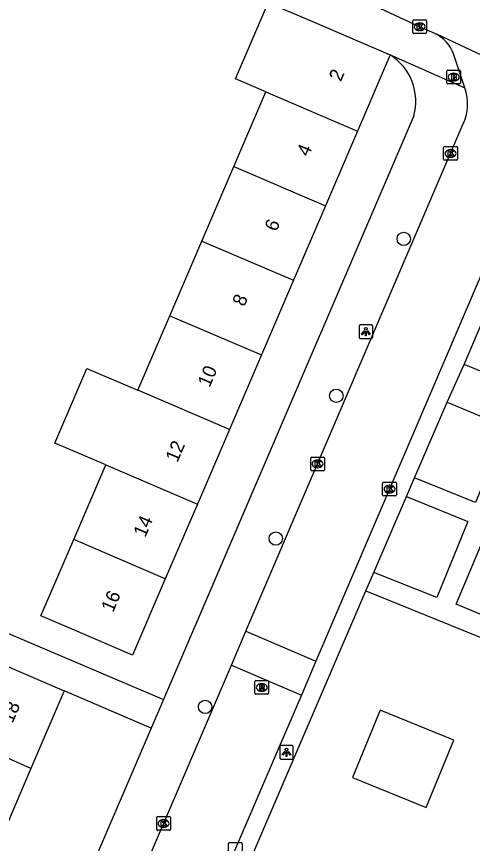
# Model space of a CAD drawing. Extents: x 159822 to 160765, y 380693 to 381634.
# Drawn here: x 160286.1 to 160319.4, y 381375.7 to 381436.2 of the extents above; entities that cross this region are included whole.
import ezdxf

# ---------------------------------------------------------------- set-up
doc = ezdxf.new("R2010")
doc.units = 0
for name, color, linetype in [('IMGEO_Boom', 7, 'Continuous'), ('IMGEO_Brandkraan', 7, 'Continuous'), ('IMGEO_Groenvoorziening', 7, 'Continuous'), ('IMGEO_Kolk', 7, 'Continuous'), ('IMGEO_Lichtpunt', 7, 'Continuous'), ('IMGEO_Pand', 7, 'Continuous'), ('IMGEO_Pand_nummerreeks', 7, 'Continuous'), ('IMGEO_Rijbaan_lokaal_open', 7, 'Continuous'), ('IMGEO_Rioolput', 7, 'Continuous'), ('IMGEO_Voetpad_halfverhard', 7, 'Continuous'), ('IMGEO_Voetpad_open', 7, 'Continuous')]:
    doc.layers.add(name, color=color, linetype=linetype)

msp = doc.modelspace()

# ---------------------------------------------------------------- linework, layer by layer
at = {"layer": 'IMGEO_Boom'}
for centre in [(160314.417, 381419.913), (160309.493, 381408.449), (160305.067, 381398.011), (160299.908, 381385.701)]:
    msp.add_circle(centre, 0.489, dxfattribs=at)
at = {"layer": 'IMGEO_Brandkraan'}
for p, q in [((160317.573, 381431.316), (160317.573, 381432.168)), ((160317.648, 381432.242), (160318.5, 381432.242)), ((160318.061, 381432.022), (160318.086, 381432.022)), ((160318.574, 381432.168), (160318.574, 381431.316)), ((160318.084, 381431.462), (160318.059, 381431.462)), ((160318.5, 381431.242), (160317.648, 381431.242))]:
    msp.add_line(p, q, dxfattribs=at)
for points in [[(160317.573, 381431.316), (160317.573, 381432.168)], [(160317.648, 381432.242), (160318.5, 381432.242)], [(160318.574, 381432.168), (160318.574, 381431.316)], [(160317.921, 381431.942), (160317.921, 381431.542), (160318.134, 381431.542)], [(160318.152, 381431.942), (160317.921, 381431.942)], [(160318.1, 381431.861), (160318.046, 381431.861), (160318.046, 381431.785)], [(160318.046, 381431.785), (160318.099, 381431.785)], [(160318.108, 381431.709), (160318.046, 381431.709), (160318.046, 381431.628)], [(160318.046, 381431.628), (160318.108, 381431.628)], [(160318.5, 381431.242), (160317.648, 381431.242)]]:
    msp.add_lwpolyline(points, dxfattribs=at)
for centre, radius, start, end in [((160317.65, 381432.166), 0.0765, 91.55205, 178.44795), ((160317.65, 381432.166), 0.0765, 91.55205, 178.44795), ((160318.498, 381432.166), 0.0765, 1.55205, 88.44795), ((160318.498, 381432.166), 0.0765, 1.55205, 88.44795), ((160318.101, 381431.823), 0.0379, 267.82845, 90.93552), ((160318.109, 381431.668), 0.0404, 269.87594, 90.50774), ((160318.14, 381431.793), 0.251, 268.66757, 293.53466), ((160318.156, 381431.797), 0.145, 59.4692, 91.53667), ((160318.181, 381431.844), 0.0922, 285.51372, 58.15012), ((160318.186, 381431.652), 0.105, 301.31148, 78.98903), ((160317.65, 381431.318), 0.0765, 181.55205, 268.44795), ((160317.65, 381431.318), 0.0765, 181.55205, 268.44795), ((160318.498, 381431.318), 0.0765, 271.55205, 358.44795), ((160318.498, 381431.318), 0.0765, 271.55205, 358.44795)]:
    msp.add_arc(centre, radius, start, end, dxfattribs=at)
for centre, major_axis, ratio, start_param, end_param in [((160318.06, 381431.742), (-0.387, 0.002), 0.722429, 4.712389, 7.853982), ((160318.085, 381431.742), (-0.39, 0.002), 0.717154, 1.570796, 4.712389)]:
    msp.add_ellipse(centre, major_axis=major_axis, ratio=ratio, start_param=start_param, end_param=end_param, dxfattribs=at)
at = {"layer": 'IMGEO_Groenvoorziening'}
msp.add_lwpolyline([(160318.08, 381383.265), (160312.7, 381385.47), (160310.683, 381380.55), (160316.062, 381378.345), (160318.08, 381383.265)], dxfattribs=at)
at = {"layer": 'IMGEO_Kolk'}
for p, q in [((160315.082, 381435), (160315.082, 381435.852)), ((160315.157, 381435.926), (160316.009, 381435.926)), ((160315.57, 381435.706), (160315.595, 381435.706)), ((160316.083, 381435.852), (160316.083, 381435)), ((160315.593, 381435.146), (160315.568, 381435.146)), ((160316.009, 381434.926), (160315.157, 381434.926)), ((160317.336, 381425.736), (160317.336, 381426.588)), ((160317.411, 381426.662), (160318.263, 381426.662)), ((160318.337, 381426.588), (160318.337, 381425.736)), ((160317.824, 381426.442), (160317.849, 381426.442)), ((160318.263, 381425.662), (160317.411, 381425.662)), ((160317.847, 381425.882), (160317.822, 381425.882)), ((160307.621, 381403.041), (160307.621, 381403.893)), ((160307.696, 381403.967), (160308.548, 381403.967)), ((160308.109, 381403.747), (160308.134, 381403.747)), ((160308.622, 381403.893), (160308.622, 381403.041)), ((160308.548, 381402.967), (160307.696, 381402.967)), ((160308.132, 381403.187), (160308.107, 381403.187)), ((160312.879, 381401.199), (160312.879, 381402.051)), ((160312.954, 381402.125), (160313.806, 381402.125)), ((160313.367, 381401.905), (160313.392, 381401.905)), ((160313.88, 381402.051), (160313.88, 381401.199)), ((160313.39, 381401.345), (160313.365, 381401.345)), ((160313.806, 381401.125), (160312.954, 381401.125)), ((160296.368, 381376.754), (160296.368, 381377.606)), ((160296.443, 381377.68), (160297.295, 381377.68)), ((160297.369, 381377.606), (160297.369, 381376.754)), ((160296.856, 381377.46), (160296.881, 381377.46)), ((160297.295, 381376.68), (160296.443, 381376.68)), ((160296.879, 381376.9), (160296.854, 381376.9)), ((160301.681, 381375.794), (160302.533, 381375.794)), ((160301.606, 381374.868), (160301.606, 381375.72)), ((160302.607, 381375.72), (160302.607, 381374.868))]:
    msp.add_line(p, q, dxfattribs=at)
for points in [[(160315.082, 381435), (160315.082, 381435.852)], [(160315.157, 381435.926), (160316.009, 381435.926)], [(160315.403, 381435.626), (160315.526, 381435.626), (160315.526, 381435.475), (160315.656, 381435.626), (160315.82, 381435.626), (160315.674, 381435.475), (160315.827, 381435.226), (160315.675, 381435.226), (160315.59, 381435.39), (160315.526, 381435.323), (160315.526, 381435.226), (160315.403, 381435.226), (160315.403, 381435.626)], [(160316.083, 381435.852), (160316.083, 381435)], [(160316.009, 381434.926), (160315.157, 381434.926)], [(160317.336, 381425.736), (160317.336, 381426.588)], [(160317.411, 381426.662), (160318.263, 381426.662)], [(160318.337, 381426.588), (160318.337, 381425.736)], [(160317.657, 381426.362), (160317.78, 381426.362), (160317.78, 381426.211), (160317.91, 381426.362), (160318.074, 381426.362), (160317.928, 381426.211), (160318.081, 381425.962), (160317.929, 381425.962), (160317.844, 381426.126), (160317.78, 381426.059), (160317.78, 381425.962), (160317.657, 381425.962), (160317.657, 381426.362)], [(160318.263, 381425.662), (160317.411, 381425.662)], [(160307.621, 381403.041), (160307.621, 381403.893)], [(160307.696, 381403.967), (160308.548, 381403.967)], [(160307.942, 381403.667), (160308.065, 381403.667), (160308.065, 381403.516), (160308.195, 381403.667), (160308.359, 381403.667), (160308.213, 381403.516), (160308.366, 381403.267), (160308.214, 381403.267), (160308.129, 381403.431), (160308.065, 381403.364), (160308.065, 381403.267), (160307.942, 381403.267), (160307.942, 381403.667)], [(160308.622, 381403.893), (160308.622, 381403.041)], [(160308.548, 381402.967), (160307.696, 381402.967)], [(160312.879, 381401.199), (160312.879, 381402.051)], [(160312.954, 381402.125), (160313.806, 381402.125)], [(160313.2, 381401.825), (160313.323, 381401.825), (160313.323, 381401.674), (160313.453, 381401.825), (160313.617, 381401.825), (160313.471, 381401.674), (160313.624, 381401.425), (160313.472, 381401.425), (160313.387, 381401.589), (160313.323, 381401.522), (160313.323, 381401.425), (160313.2, 381401.425), (160313.2, 381401.825)], [(160313.88, 381402.051), (160313.88, 381401.199)], [(160313.806, 381401.125), (160312.954, 381401.125)], [(160296.368, 381376.754), (160296.368, 381377.606)], [(160296.443, 381377.68), (160297.295, 381377.68)], [(160297.369, 381377.606), (160297.369, 381376.754)], [(160296.689, 381377.38), (160296.812, 381377.38), (160296.812, 381377.229), (160296.942, 381377.38), (160297.106, 381377.38), (160296.96, 381377.229), (160297.113, 381376.98), (160296.961, 381376.98), (160296.876, 381377.144), (160296.812, 381377.077), (160296.812, 381376.98), (160296.689, 381376.98), (160296.689, 381377.38)], [(160297.295, 381376.68), (160296.443, 381376.68)], [(160301.681, 381375.794), (160302.533, 381375.794)], [(160301.606, 381374.868), (160301.606, 381375.72)], [(160302.607, 381375.72), (160302.607, 381374.868)]]:
    msp.add_lwpolyline(points, dxfattribs=at)
for centre, start, end in [((160315.159, 381435.85), 91.55205, 178.44795), ((160315.159, 381435.85), 91.55205, 178.44795), ((160316.007, 381435.85), 1.55205, 88.44795), ((160316.007, 381435.85), 1.55205, 88.44795), ((160315.159, 381435.002), 181.55205, 268.44795), ((160315.159, 381435.002), 181.55205, 268.44795), ((160316.007, 381435.002), 271.55205, 358.44795), ((160316.007, 381435.002), 271.55205, 358.44795), ((160317.413, 381426.586), 91.55205, 178.44795), ((160317.413, 381426.586), 91.55205, 178.44795), ((160318.261, 381426.586), 1.55205, 88.44795), ((160318.261, 381426.586), 1.55205, 88.44795), ((160317.413, 381425.738), 181.55205, 268.44795), ((160317.413, 381425.738), 181.55205, 268.44795), ((160318.261, 381425.738), 271.55205, 358.44795), ((160318.261, 381425.738), 271.55205, 358.44795), ((160307.698, 381403.891), 91.55205, 178.44795), ((160307.698, 381403.891), 91.55205, 178.44795), ((160308.546, 381403.891), 1.55205, 88.44795), ((160308.546, 381403.891), 1.55205, 88.44795), ((160307.698, 381403.043), 181.55205, 268.44795), ((160307.698, 381403.043), 181.55205, 268.44795), ((160308.546, 381403.043), 271.55205, 358.44795), ((160308.546, 381403.043), 271.55205, 358.44795), ((160312.956, 381402.049), 91.55205, 178.44795), ((160312.956, 381402.049), 91.55205, 178.44795), ((160313.804, 381402.049), 1.55205, 88.44795), ((160313.804, 381402.049), 1.55205, 88.44795), ((160312.956, 381401.201), 181.55205, 268.44795), ((160312.956, 381401.201), 181.55205, 268.44795), ((160313.804, 381401.201), 271.55205, 358.44795), ((160313.804, 381401.201), 271.55205, 358.44795), ((160296.445, 381377.604), 91.55205, 178.44795), ((160296.445, 381377.604), 91.55205, 178.44795), ((160297.293, 381377.604), 1.55205, 88.44795), ((160297.293, 381377.604), 1.55205, 88.44795), ((160296.445, 381376.756), 181.55205, 268.44795), ((160296.445, 381376.756), 181.55205, 268.44795), ((160297.293, 381376.756), 271.55205, 358.44795), ((160297.293, 381376.756), 271.55205, 358.44795), ((160301.683, 381375.718), 91.55205, 178.44795), ((160301.683, 381375.718), 91.55205, 178.44795), ((160302.531, 381375.718), 1.55205, 88.44795), ((160302.531, 381375.718), 1.55205, 88.44795)]:
    msp.add_arc(centre, 0.0765, start, end, dxfattribs=at)
for centre, major_axis, ratio, start_param, end_param in [((160315.569, 381435.426), (-0.387, 0.002), 0.722429, 4.712389, 7.853982), ((160315.594, 381435.426), (-0.39, 0.002), 0.717154, 1.570796, 4.712389), ((160317.823, 381426.162), (-0.387, 0.002), 0.722429, 4.712389, 7.853982), ((160317.848, 381426.162), (-0.39, 0.002), 0.717154, 1.570796, 4.712389), ((160308.108, 381403.467), (-0.387, 0.002), 0.722429, 4.712389, 7.853982), ((160308.133, 381403.467), (-0.39, 0.002), 0.717154, 1.570796, 4.712389), ((160313.366, 381401.625), (-0.387, 0.002), 0.722429, 4.712389, 7.853982), ((160313.391, 381401.625), (-0.39, 0.002), 0.717154, 1.570796, 4.712389), ((160296.855, 381377.18), (-0.387, 0.002), 0.722429, 4.712389, 7.853982), ((160296.88, 381377.18), (-0.39, 0.002), 0.717154, 1.570796, 4.712389)]:
    msp.add_ellipse(centre, major_axis=major_axis, ratio=ratio, start_param=start_param, end_param=end_param, dxfattribs=at)
at = {"layer": 'IMGEO_Lichtpunt'}
for p, q in [((160311.155, 381413.539), (160311.155, 381412.732)), ((160311.155, 381413.539), (160311.155, 381412.732)), ((160312.057, 381413.634), (160311.249, 381413.634)), ((160312.057, 381413.634), (160311.249, 381413.634)), ((160312.151, 381412.732), (160312.151, 381413.539)), ((160312.151, 381412.732), (160312.151, 381413.539)), ((160311.249, 381412.638), (160312.057, 381412.638)), ((160311.249, 381412.638), (160312.057, 381412.638)), ((160305.355, 381382.791), (160305.355, 381381.984)), ((160305.355, 381382.791), (160305.355, 381381.984)), ((160306.257, 381382.886), (160305.449, 381382.886)), ((160306.257, 381382.886), (160305.449, 381382.886)), ((160306.351, 381381.984), (160306.351, 381382.791)), ((160306.351, 381381.984), (160306.351, 381382.791)), ((160305.449, 381381.89), (160306.257, 381381.89)), ((160305.449, 381381.89), (160306.257, 381381.89))]:
    msp.add_line(p, q, dxfattribs=at)
for points in [[(160311.529, 381413.203), (160311.568, 381413.175), (160311.38, 381412.913), (160311.342, 381412.94), (160311.529, 381413.203)], [(160311.631, 381413.155), (160311.678, 381413.155), (160311.678, 381412.833), (160311.631, 381412.833), (160311.631, 381413.155)], [(160311.741, 381413.175), (160311.779, 381413.202), (160311.966, 381412.94), (160311.927, 381412.912), (160311.741, 381413.175)], [(160305.729, 381382.455), (160305.768, 381382.427), (160305.58, 381382.165), (160305.542, 381382.192), (160305.729, 381382.455)], [(160305.831, 381382.407), (160305.878, 381382.407), (160305.878, 381382.085), (160305.831, 381382.085), (160305.831, 381382.407)], [(160305.941, 381382.427), (160305.979, 381382.454), (160306.166, 381382.192), (160306.127, 381382.164), (160305.941, 381382.427)]]:
    msp.add_lwpolyline(points, dxfattribs=at)
for centre in [(160311.654, 381413.337), (160305.854, 381382.589)]:
    msp.add_circle(centre, 0.0994, dxfattribs=at)
for centre, start, end in [((160311.249, 381413.539), 90, 180), ((160311.249, 381413.539), 90, 180), ((160312.057, 381413.539), 0, 90), ((160312.057, 381413.539), 0, 90), ((160311.249, 381412.732), 180, 270), ((160311.249, 381412.732), 180, 270), ((160312.057, 381412.732), 270, 0), ((160312.057, 381412.732), 270, 360), ((160305.449, 381382.791), 90, 180), ((160305.449, 381382.791), 90, 180), ((160306.257, 381382.791), 0, 90), ((160306.257, 381382.791), 0, 90), ((160305.449, 381381.984), 180, 270), ((160305.449, 381381.984), 180, 270), ((160306.257, 381381.984), 270, 0), ((160306.257, 381381.984), 270, 360)]:
    msp.add_arc(centre, 0.0946, start, end, dxfattribs=at)
at = {"layer": 'IMGEO_Pand'}
for points in [[(160304.341, 381430.67), (160302.13, 381431.618), (160304.52, 381437.183), (160306.728, 381436.236)], [(160306.728, 381436.236), (160313.423, 381433.365)], [(160313.423, 381433.365), (160311.036, 381427.8)], [(160302.002, 381425.214), (160304.341, 381430.67)], [(160304.341, 381430.67), (160311.036, 381427.8)], [(160311.036, 381427.8), (160308.697, 381422.344)], [(160299.662, 381419.759), (160302.002, 381425.214)], [(160302.002, 381425.214), (160308.697, 381422.344)], [(160308.697, 381422.344), (160306.357, 381416.888)], [(160297.323, 381414.303), (160299.662, 381419.759)], [(160299.662, 381419.759), (160306.357, 381416.888)], [(160306.357, 381416.888), (160304.018, 381411.433)], [(160294.983, 381408.847), (160297.323, 381414.303)], [(160297.323, 381414.303), (160304.018, 381411.433)], [(160304.018, 381411.433), (160301.678, 381405.977)], [(160292.644, 381403.393), (160288.918, 381404.991), (160291.257, 381410.444), (160294.983, 381408.847)], [(160301.678, 381405.977), (160294.983, 381408.847)], [(160301.678, 381405.977), (160299.339, 381400.522)], [(160290.304, 381397.937), (160292.644, 381403.393)], [(160292.644, 381403.393), (160299.339, 381400.522)], [(160299.339, 381400.522), (160297, 381395.067)], [(160297, 381395.067), (160294.611, 381389.497), (160290.016, 381391.468), (160287.916, 381392.368), (160290.304, 381397.937)], [(160297, 381395.067), (160290.304, 381397.937)], [(160282.945, 381389.736), (160285.019, 381388.847), (160289.614, 381386.877)], [(160289.614, 381386.877), (160287.184, 381381.211)], [(160287.184, 381381.211), (160280.556, 381384.165)], [(160287.184, 381381.211), (160284.845, 381375.755)]]:
    msp.add_lwpolyline(points, dxfattribs=at)
at = {"layer": 'IMGEO_Rijbaan_lokaal_open'}
for points in [[(160316.693, 381434.93), (160315.583, 381435.427), (160298.734, 381443.299), (160298.42, 381443.452)], [(160316.693, 381434.93), (160316.801, 381434.899), (160331.345, 381428.063)], [(160318.874, 381430.953), (160318.052, 381433.435)], [(160302.891, 381391.245), (160318.741, 381428.27)], [(160323.46, 381425.204), (160308.006, 381389.055)], [(160301.828, 381388.763), (160302.891, 381391.245)], [(160302.891, 381391.245), (160308.006, 381389.055)], [(160308.006, 381389.055), (160306.945, 381386.573)], [(160277.958, 381333.106), (160288.047, 381356.571), (160301.828, 381388.763)], [(160301.828, 381388.763), (160306.945, 381386.573)], [(160306.945, 381386.573), (160305.25, 381382.609), (160283.033, 381330.923)]]:
    msp.add_lwpolyline(points, dxfattribs=at)
for centre, radius, start, end in [((160315.563, 381432.537), 2.646, 19.82799, 64.71557), ((160315.751, 381429.763), 3.342, 333.46196, 20.86222)]:
    msp.add_arc(centre, radius, start, end, dxfattribs=at)
at = {"layer": 'IMGEO_Rioolput'}
for p, q in [((160303.549, 381386.7), (160303.549, 381387.552)), ((160303.624, 381387.626), (160304.476, 381387.626)), ((160304.037, 381387.406), (160304.062, 381387.406)), ((160304.55, 381387.552), (160304.55, 381386.7)), ((160304.06, 381386.846), (160304.035, 381386.846)), ((160304.476, 381386.626), (160303.624, 381386.626))]:
    msp.add_line(p, q, dxfattribs=at)
for points in [[(160303.549, 381386.7), (160303.549, 381387.552)], [(160303.624, 381387.626), (160304.476, 381387.626)], [(160304.138, 381387.324), (160303.886, 381387.326), (160303.886, 381386.926)], [(160304.064, 381387.245), (160304.01, 381387.245), (160304.01, 381387.164)], [(160304.55, 381387.552), (160304.55, 381386.7)], [(160303.886, 381386.926), (160304.01, 381386.926), (160304.01, 381387.088), (160304.021, 381387.088)], [(160304.01, 381387.164), (160304.062, 381387.164)], [(160304.068, 381387.059), (160304.139, 381386.926), (160304.279, 381386.926), (160304.214, 381387.052)], [(160304.476, 381386.626), (160303.624, 381386.626)]]:
    msp.add_lwpolyline(points, dxfattribs=at)
for centre, radius, start, end in [((160303.626, 381387.55), 0.0765, 91.55205, 178.44795), ((160303.626, 381387.55), 0.0765, 91.55205, 178.44795), ((160304.07, 381387.149), 0.0964, 77.00612, 93.18647), ((160304.084, 381387.206), 0.0378, 276.66336, 79.67722), ((160304.137, 381387.214), 0.109, 350.36119, 89.41601), ((160304.474, 381387.55), 0.0765, 1.55205, 88.44795), ((160304.474, 381387.55), 0.0765, 1.55205, 88.44795), ((160303.626, 381386.702), 0.0765, 181.55205, 268.44795), ((160303.626, 381386.702), 0.0765, 181.55205, 268.44795), ((160304.02, 381387.035), 0.0533, 26.02933, 88.69889), ((160304.046, 381387.353), 0.19, 274.7715, 282.96867), ((160304.135, 381387.214), 0.112, 277.58423, 350.98172), ((160304.119, 381386.999), 0.108, 29.51342, 73.79051), ((160304.474, 381386.702), 0.0765, 271.55205, 358.44795), ((160304.474, 381386.702), 0.0765, 271.55205, 358.44795)]:
    msp.add_arc(centre, radius, start, end, dxfattribs=at)
for centre, major_axis, ratio, start_param, end_param in [((160304.036, 381387.126), (-0.387, 0.002), 0.722429, 4.712389, 7.853982), ((160304.061, 381387.126), (-0.39, 0.002), 0.717154, 1.570796, 4.712389)]:
    msp.add_ellipse(centre, major_axis=major_axis, ratio=ratio, start_param=start_param, end_param=end_param, dxfattribs=at)
at = {"layer": 'IMGEO_Voetpad_halfverhard'}
for points in [[(160263.003, 381402.416), (160263.263, 381402.295), (160262.575, 381400.815), (160272.062, 381396.784), (160296.864, 381386.245)], [(160295.966, 381384.153), (160289.614, 381386.877)]]:
    msp.add_lwpolyline(points, dxfattribs=at)
at = {"layer": 'IMGEO_Voetpad_open'}
for points in [[(160313.423, 381433.365), (160318.874, 381430.953)], [(160315.157, 381428.903), (160296.864, 381386.245)], [(160318.838, 381410.743), (160322.466, 381419.271), (160324.576, 381424.229)], [(160317.588, 381407.992), (160318.838, 381410.743)], [(160326.286, 381407.712), (160318.838, 381410.743)], [(160315.206, 381402.446), (160317.588, 381407.992)], [(160317.588, 381407.992), (160321.903, 381406.187), (160319.673, 381400.657), (160315.206, 381402.446)], [(160314.619, 381401.078), (160315.206, 381402.446)], [(160312.241, 381395.538), (160314.619, 381401.078)], [(160314.619, 381401.078), (160319.101, 381399.256), (160316.836, 381393.709), (160312.241, 381395.538)], [(160326.06, 381396.436), (160323.762, 381390.917), (160318.258, 381393.208), (160320.556, 381398.727), (160326.06, 381396.436)], [(160311.657, 381394.179), (160312.241, 381395.538)], [(160274.636, 381307.919), (160311.657, 381394.179)], [(160311.657, 381394.179), (160335.491, 381384.517)], [(160296.864, 381386.245), (160295.966, 381384.153)], [(160295.966, 381384.153), (160263.116, 381307.549)]]:
    msp.add_lwpolyline(points, dxfattribs=at)
msp.add_arc((160311.296, 381429.97), 4.006, 344.54554, 57.9282, dxfattribs=at)

# ---------------------------------------------------------------- texts
at = {"layer": 'IMGEO_Pand_nummerreeks'}
for s, rotation, p in [('2', 66.78969, (160309.822, 381431.362)), ('4', 66.7888, (160307.471, 381425.88)), ('6', 66.7888, (160305.12, 381420.396)), ('8', 66.7888, (160302.77, 381414.916)), ('10', 66.7888, (160300.236, 381409.009)), ('12', 66.78969, (160297.882, 381403.521)), ('14', 66.7888, (160295.532, 381398.04)), ('16', 66.7888, (160293.18, 381392.557)), ('18', 66.78868, (160285.836, 381384.461))]:
    msp.add_text(s, height=1, rotation=rotation, dxfattribs=at).set_placement(p)

doc.saveas('drawing.dxf')
